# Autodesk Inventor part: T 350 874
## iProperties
Company: Mayer & Müller AG Schaltgeräte
Created: 2005-12
Part Number: T 350 874
Material: 2.0060.30
Description: Hauptkontakt - DC
Document SubType Name: Modeling
Designer: I.Baliuc
Manufacturer: Standard
Standards Organization: Custom
Density: 8.94 g/cm^3
Zweck: 3150 + HSLT (Links / Rechts)
Author: T.Messerschmitt
Revision Number: 350874
Keywords: 382072
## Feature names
1. Extrusion2
2. Bohrung1 [Hole]
3. Bohrung2 [Hole]
4. Extrusion3
5. Extrusion4
6. Rundung4 [Fillet]
7. Bohrung3 [Hole]
